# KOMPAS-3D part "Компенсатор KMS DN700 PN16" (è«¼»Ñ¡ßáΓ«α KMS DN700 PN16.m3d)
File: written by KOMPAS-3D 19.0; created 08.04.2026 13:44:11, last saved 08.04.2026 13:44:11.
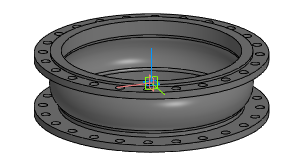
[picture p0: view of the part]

Document properties: Автор: Энергия; Полное имя файла: Z:\3.Личные\kachalov\3d для проектировщиков\7.1 Компенсатор\stp_Компенсатор KSM\Компенсатор KMS DN700 PN16.m3d

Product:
- Part/product: Компенсатор KMS DN700 PN16

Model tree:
1. Операция без истории:1  (labels: Компенсатор KMS DN700 PN16)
